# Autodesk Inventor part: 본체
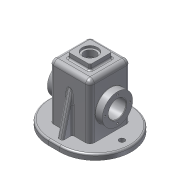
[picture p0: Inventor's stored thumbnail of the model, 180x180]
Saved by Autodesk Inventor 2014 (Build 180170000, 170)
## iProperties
Created: 2017-07
Part Number: 본체
Material: 알루미늄 6061
Document SubType Name: Modeling
Designer: user
Mass: 983.368 g
Surface Area: 989.873 cm^2
Volume: 362.867 cm^3
Density: 2.71 g/cm^3
Appearance: 알루미늄 - 평지
Author: user
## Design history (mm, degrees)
sketch "스케치1"
  geometry: L1 (0, 0)-(74, 0); L2 (74, 0)-(74, 110); L3 (74, 110)-(0, 110); L4 (0, 110)-(0, 0)
  constraints: 8 end point, 2 parallel, 1 horizontal, 1 perpendicular
  dimensions: "d0" = 74 distance of L2.end L3.end; "d1" = 110 distance of L1.end L2.end
extrude "돌출1" new body sketch "스케치1" stored distance "d2" = 74; taper "d3" = 0 deg
node "작업 평면1"
sketch "스케치3"
  geometry: L1 (-112, 65)-(38, 65); L2 (38, 65)-(38, -65); L3 (38, -65)-(-112, -65); L4 (-112, -65)-(-112, 65); L5 (0, 37)-(-74, 37) reference; 4 further points
  constraints: 8 end point, 3 midpoint, 2 parallel, 1 horizontal, 1 horizontal alignment, 1 perpendicular, 1 vertical alignment
  dimensions: "d5" = 150 distance of L1.start L1.end; "d6" = 130 distance of L1.end L2.end
extrude "돌출2" join sketch "스케치3" distance "d7" = 10; taper "d8" = 0 deg
sketch "스케치4"
  geometry: L1 (0, 110)-(74, 110) reference; L2 (0, 10)-(0, 110) reference; L3 (74, 110)-(74, 10) reference; L4 (67, 0)-(67, 105); L5 (67, 105)-(7, 105); L6 (7, 105)-(7, 0); L7 (-38, 0)-(112, 0) reference; L8 (7, 0)-(67, 0); 1 further point
  constraints: 8 end point, 2 point on line, 1 collinear
  dimensions: "d9" = 7 distance between parallel lines of L3 L4; "d122" = 5 distance between parallel lines of L1 L5
extrude "돌출4" cut sketch "스케치4" stored distance "d12" = 64; taper "d13" = 0 deg
sketch "스케치5"
  geometry: L1 (74, 110)-(74, 10) reference; L2 (5.906, 55)-(74, 55); L3 (87, 55)-(87, 82.5); L4 (87, 82.5)-(74, 82.5); L5 (60, 68.5)-(74, 82.5); L6 (60, 68.5)-(60, 55); L7 (87, 55)-(74, 55); L8 (-13, 82.5)-(-13, 55); L9 (5.906, 55)-(-13, 55); L10 (7, 0)-(7, 105) reference; L11 (67, 105)-(67, 0) reference; L12 (-38, 0)-(112, 0) reference; L13 (-13, 82.5)-(0, 82.5); L14 (0, 82.5)-(14, 68.5); L15 (14, 55)-(14, 68.5); 3 further points
  constraints: 22 end point, 7 perpendicular, 4 point on line, 2 midpoint, 1 parallel
  dimensions: "d17" = 13 distance between parallel lines of L1 L3; "d18" = 100 distance between parallel lines of L3 L8; "d20" = 7 distance between parallel lines of L11 L6; "d22" = 55 diameter of L4 L7; "d23" = 55 distance between parallel lines of L12 L9; "d25" = 135 deg angle of L11 L5; "d27" = 68.09363 distance from line of L2.start L1; "d95" = 135 deg angle of L10 L14 (derived); "d96" = 55 diameter of L13 L2; "d97" = 7 distance between parallel lines of L10 L15; "d98" = 20.85965 distance from line of L12.end L14
revolve "회전1" sketch "스케치5" stored, may be unused: angle "d28" = 90 deg
sketch "스케치6"
  geometry: L1 (17, 57)-(57, 57); L2 (57, 57)-(57, 17); L3 (57, 17)-(17, 17); L4 (17, 17)-(17, 57); L5 (17, 57)-(57, 17); L6 (57, 57)-(17, 17); L7 (112, -28)-(-38, -28) reference; L8 (112, 102)-(112, -28) reference; 2 further points
  constraints: 12 end point, 2 midpoint, 2 parallel, 1 horizontal, 1 perpendicular
  dimensions: "d29" = 65 distance from line of L7 point (37, 37); "d30" = 75 distance from line of L8 point (37, 37); "d31" = 40 distance of L1.end L2.end; "d32" = 40 distance of L2.end L3.end
extrude "돌출5" join sketch "스케치6" distance "d33" = 10; taper "d34" = 0 deg
fillet "모깎기1" dims "d35" = 8
fillet "모깎기3" dims "d37" = 3
fillet "모깎기4" dims "d38" = 3
sketch "스케치7"
  geometry: L1 (54, 57)-(20, 57) reference; L2 (17, 54)-(17, 20) reference; L3 (20, 17)-(54, 17) reference; L4 (57, 20)-(57, 54) reference; L5 (17, 37)-(57, 37); L6 (37, 57)-(37, 17); 4 further points
  constraints: 5 midpoint, 4 end point, 2 coincident
hole "구멍1" sketch "스케치7" at (37, 37) diameter "d39" = 21; stored, may be unused: countersink angle "d43" = 90 deg, drill point angle "d45" = 118 deg; dims "d40" = 6, "d41" = 28, "d42" = 4, "d44" = 8
node "작업 평면3"
  node "작업 평면2"
sketch "스케치8"
  geometry: L1 (10, 37)-(110, 37) reference; L2 (110, -37)-(10, -37) reference; L3 (82.194, -37)-(10, -55); L4 (6.545, -65)-(55.596, -65); L5 (82.194, -37)-(10, -37); 2 further points
  constraints: 6 end point, 1 collinear, 1 point on line
  dimensions: "d49" = 14 deg angle of L4 L3; "d61" = 10 distance of point (10, -65) L3.end
fillet "모깎기5"
fillet "모깎기6"
feature "리브1" dims "d62" = 1, "d63" = 10, "d64" = 0, "d65" = 0, "d66" = 1, "d67" = 1
fillet "모깎기8" dims "d69" = 3
sketch "스케치9" dims "d70" = 45
  geometry: C1 r 27.5 at (0, 0) reference; 3 further points
  constraints: 1 coincident, 1 vertical alignment, 2 other
hole "구멍3" sketch "스케치9" at (0, 22.5) diameter "d71" = 3.242; stored, may be unused: countersink angle "d75" = 90 deg, drill point angle "d77" = 118 deg; dims "d72" = 8, "d73" = 28, "d74" = 4, "d76" = 10
fillet "모깎기10" dims "d82" = 0.5
fillet "모깎기11" dims "d83" = 0.5
fillet "모깎기12" dims "d84" = 3
fillet "모깎기13" dims "d85" = 3
sketch "스케치10"
  geometry: L1 (-46, 110)-(-12, 110) reference; L2 (8, 0)-(8, 100) reference; 2 further points
  constraints: 1 other
  dimensions: "d87" = 30 distance from line of L1 point (-29, 80); "d88" = 37 distance from line of L2 point (-29, 80)
fillet "모깎기15" dims "d89" = 8
feature "엠보싱1" dims "d90" = 0.5, "d91" = 0
hole "구멍4" diameter "d101" = 32; stored, may be unused: countersink angle "d105" = 90 deg, drill point angle "d107" = 0 deg; dims "d99" = 10, "d100" = 10, "d102" = 6, "d103" = 4, "d104" = 2, "d106" = 8
chamfer "모따기1" distance "d108" = 1; stored, may be unused: second distance "d109" = 2, angle "d110" = 45 deg
sketch "스케치11"
  geometry: L1 (47, -62)-(27, -62) reference; L2 (27, 62)-(47, 62) reference; L3 (37, 62)-(37, -62); L4 (-35, 0)-(109, 0); L5 (95, 18.716)-(95, -18.716); L6 (-21, 18.716)-(-21, -18.716); A1 r 62 centre (47, 0) between (47, -62) and (47, 62) reference; A2 r 62 centre (27, 0) between (27, 62) and (27, -62) reference; 3 further points
  constraints: 8 end point, 4 midpoint, 2 point on circle, 2 symmetric about line, 1 perpendicular
  dimensions: "d114" = 58 distance between parallel lines of L3 L5
hole "구멍5" sketch "스케치11" at (95, 0), (-21, 0) diameter "d115" = 10; stored, may be unused: countersink angle "d119" = 90 deg, drill point angle "d121" = 0 deg; dims "d116" = 6, "d117" = 4, "d118" = 2, "d120" = 8
fillet "모깎기16" dims "d123" = 3
fillet "모깎기17" dims "d124" = 3
node "솔리드1"
mirror "대칭2"
pattern_circular "원형 패턴2" dims angle "d112" = 360 deg
mirror "대칭4"
other parameters: "d46" = -13
